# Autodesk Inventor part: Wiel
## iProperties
Created: 2007-06
Part Number: Wiel
Document SubType Name: Modeling
Designer: Phil Trethewie
Author: Phil Trethewie
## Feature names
1. Revolution1
2. Revolution2
